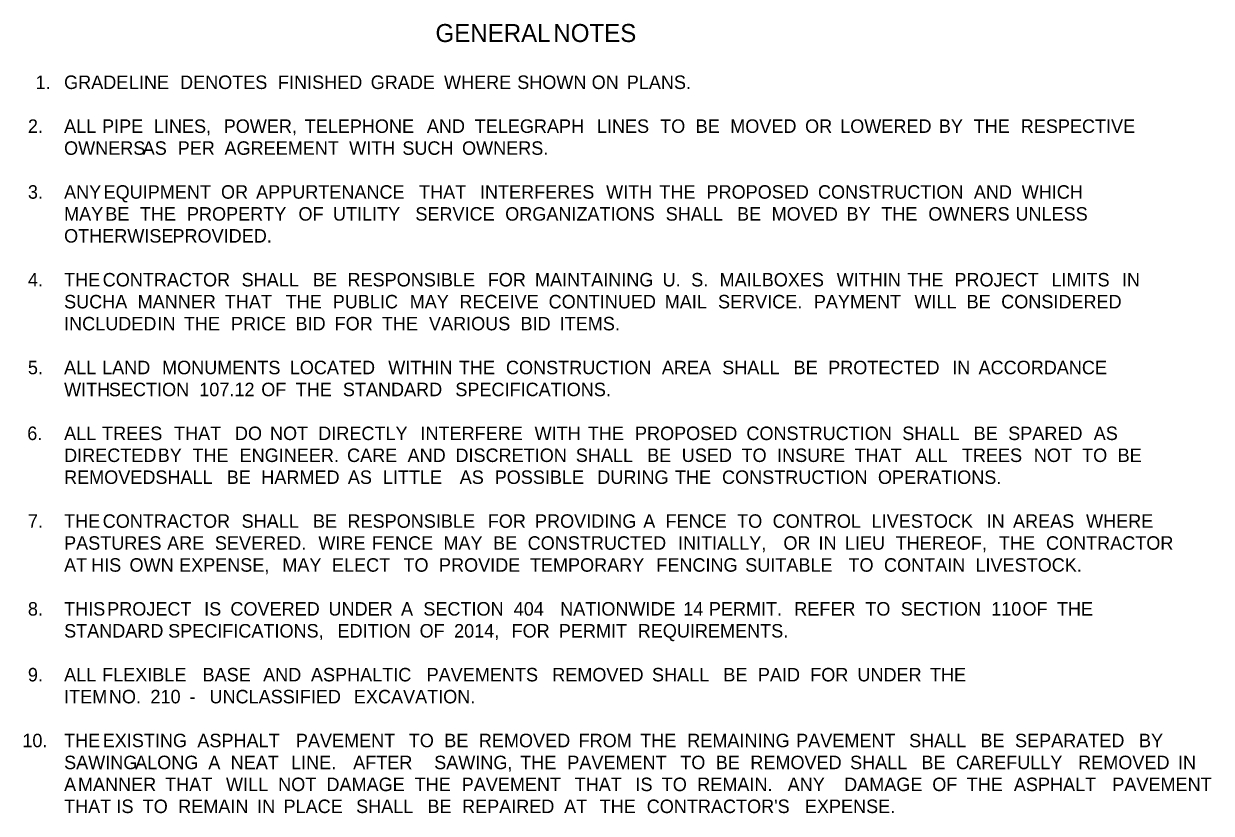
# Model space of a CAD drawing. Extents: x 1226673 to 1228148, y 151313 to 152324.
# Drawn here: x 1226673 to 1227200, y 151655 to 152006 of the extents above; entities that cross this region are included whole.
import ezdxf

# ---------------------------------------------------------------- set-up
doc = ezdxf.new("R2010")
doc.units = 0
doc.layers.add('R_Dimension', color=7, linetype='Continuous')

msp = doc.modelspace()

# ---------------------------------------------------------------- texts
at = {"layer": 'R_Dimension'}
for s, height, p in [('GENERAL', 8, (1226855.48, 151998.07)), (' NOTES', 8, (1226904.87, 151998.07)), ('1.', 6, (1226677.8, 151977.19)), ('GRADE', 6, (1226690.48, 151977.19)), (' LINE', 6, (1226717.03, 151977.19)), (' DENOTES', 6, (1226739.76, 151977.19)), (' FINISHED', 6, (1226783.27, 151977.19)), (' GRADE', 6, (1226824.47, 151977.19)), (' WHERE', 6, (1226857.02, 151977.19)), (' SHOWN', 6, (1226889.57, 151977.19)), (' ON', 6, (1226922.64, 151977.19)), (' PLANS.', 6, (1226938.23, 151977.19)), ('2.', 6, (1226674.4, 151957.69)), ('ALL', 6, (1226690.48, 151957.69)), (' PIPE', 6, (1226705.13, 151957.69)), (' LINES,', 6, (1226728.14, 151957.69)), (' POWER,', 6, (1226759.17, 151957.69)), (' TELEPHONE', 6, (1226795.13, 151957.69)), (' AND', 6, (1226849.41, 151957.69)), (' TELEGRAPH', 6, (1226870.67, 151957.69)), (' LINES', 6, (1226924.95, 151957.69)), (' TO', 6, (1226953.06, 151957.69)), (' BE', 6, (1226968.84, 151957.69)), (' MOVED', 6, (1226984.2, 151957.69)), (' OR', 6, (1227017.46, 151957.69)), (' LOWERED', 6, (1227033.05, 151957.69)), (' BY', 6, (1227076.89, 151957.69)), (' THE', 6, (1227092.34, 151957.69)), (' RESPECTIVE', 6, (1227113.27, 151957.69)), ('OWNERS', 6, (1226690.48, 151947.94)), (' AS', 6, (1226723.17, 151947.94)), (' PER', 6, (1226738.72, 151947.94)), (' AGREEMENT', 6, (1226759.51, 151947.94)), (' WITH', 6, (1226814.88, 151947.94)), (' SUCH', 6, (1226838.54, 151947.94)), (' OWNERS.', 6, (1226865.05, 151947.94)), ('3.', 6, (1226674.4, 151928.44)), ('ANY', 6, (1226690.48, 151928.44)), (' EQUIPMENT', 6, (1226705.79, 151928.44)), (' OR', 6, (1226757.95, 151928.44)), (' APPURTENANCE', 6, (1226773.54, 151928.44)), (' THAT', 6, (1226845.96, 151928.44)), (' INTERFERES', 6, (1226872.99, 151928.44)), (' WITH', 6, (1226929.06, 151928.44)), (' THE', 6, (1226952.73, 151928.44)), (' PROPOSED', 6, (1226973.66, 151928.44)), (' CONSTRUCTION', 6, (1227023.17, 151928.44)), (' AND', 6, (1227092.43, 151928.44)), (' WHICH', 6, (1227113.69, 151928.44)), ('MAY', 6, (1226690.48, 151918.69)), (' BE', 6, (1226706.54, 151918.69)), (' THE', 6, (1226721.9, 151918.69)), (' PROPERTY', 6, (1226742.83, 151918.69)), (' OF', 6, (1226792.39, 151918.69)), (' UTILITY', 6, (1226807.69, 151918.69)), (' SERVICE', 6, (1226844.31, 151918.69)), (' ORGANIZATIONS', 6, (1226884.23, 151918.69)), (' SHALL', 6, (1226955.52, 151918.69)), (' BE', 6, (1226987.22, 151918.69)), (' MOVED', 6, (1227002.58, 151918.69)), (' BY', 6, (1227035.84, 151918.69)), (' THE', 6, (1227051.29, 151918.69)), (' OWNERS', 6, (1227072.21, 151918.69)), (' UNLESS', 6, (1227110.91, 151918.69)), ('OTHERWISE', 6, (1226690.48, 151908.94)), (' PROVIDED.', 6, (1226736.4, 151908.94)), ('4.', 6, (1226674.4, 151889.44)), ('THE', 6, (1226690.48, 151889.44)), (' CONTRACTOR', 6, (1226705.41, 151889.44)), (' SHALL', 6, (1226767.11, 151889.44)), (' BE', 6, (1226798.81, 151889.44)), (' RESPONSIBLE', 6, (1226814.17, 151889.44)), (' FOR', 6, (1226876.48, 151889.44)), (' MAINTAINING', 6, (1226897.46, 151889.44)), (' U.', 6, (1226954.15, 151889.44)), (' S.', 6, (1226966.86, 151889.44)), (' MAILBOXES', 6, (1226979.47, 151889.44)), (' WITHIN', 6, (1227031.49, 151889.44)), (' THE', 6, (1227062.86, 151889.44)), (' PROJECT', 6, (1227083.79, 151889.44)), (' LIMITS', 6, (1227126.88, 151889.44)), (' IN', 6, (1227158.2, 151889.44)), ('SUCH', 6, (1226690.48, 151879.69)), (' A', 6, (1226710.99, 151879.69)), (' MANNER', 6, (1226720.91, 151879.69)), (' THAT', 6, (1226759.65, 151879.69)), (' THE', 6, (1226786.67, 151879.69)), (' PUBLIC', 6, (1226807.6, 151879.69)), (' MAY', 6, (1226841.8, 151879.69)), (' RECEIVE', 6, (1226863.87, 151879.69)), (' CONTINUED', 6, (1226903.51, 151879.69)), (' MAIL', 6, (1226955.1, 151879.69)), (' SERVICE.', 6, (1226978.77, 151879.69)), (' PAYMENT', 6, (1227021.33, 151879.69)), (' WILL', 6, (1227066.03, 151879.69)), (' BE', 6, (1227089.22, 151879.69)), (' CONSIDERED', 6, (1227104.58, 151879.69)), ('INCLUDED', 6, (1226690.48, 151869.94)), (' IN', 6, (1226729.74, 151869.94)), (' THE', 6, (1226741.46, 151869.94)), (' PRICE', 6, (1226762.39, 151869.94)), (' BID', 6, (1226791.06, 151869.94)), (' FOR', 6, (1226808.45, 151869.94)), (' THE', 6, (1226829.43, 151869.94)), (' VARIOUS', 6, (1226850.36, 151869.94)), (' BID', 6, (1226891.03, 151869.94)), (' ITEMS.', 6, (1226908.42, 151869.94)), ('5.', 6, (1226674.4, 151850.44)), ('ALL', 6, (1226690.48, 151850.44)), (' LAND', 6, (1226705.13, 151850.44)), (' MONUMENTS', 6, (1226731.77, 151850.44)), (' LOCATED', 6, (1226788.51, 151850.44)), (' WITHIN', 6, (1226832.26, 151850.44)), (' THE', 6, (1226863.63, 151850.44)), (' CONSTRUCTION', 6, (1226884.56, 151850.44)), (' AREA', 6, (1226953.82, 151850.44)), (' SHALL', 6, (1226980.66, 151850.44)), (' BE', 6, (1227012.36, 151850.44)), (' PROTECTED', 6, (1227027.71, 151850.44)), (' IN', 6, (1227082.8, 151850.44)), (' ACCORDANCE', 6, (1227094.51, 151850.44)), ('WITH', 6, (1226690.48, 151840.69)), (' SECTION', 6, (1226708.15, 151840.69)), (' 107.12', 6, (1226748.31, 151840.69)), (' OF', 6, (1226775.85, 151840.69)), (' THE', 6, (1226791.16, 151840.69)), (' STANDARD', 6, (1226812.09, 151840.69)), (' SPECIFICATIONS.', 6, (1226862.07, 151840.69)), ('6.', 6, (1226674.12, 151821.19)), ('ALL', 6, (1226690.48, 151821.19)), (' TREES', 6, (1226705.13, 151821.19)), (' THAT', 6, (1226737.11, 151821.19)), (' DO', 6, (1226764.14, 151821.19)), (' NOT', 6, (1226779.73, 151821.19)), (' DIRECTLY', 6, (1226801.17, 151821.19)), (' INTERFERE', 6, (1226846.58, 151821.19)), (' WITH', 6, (1226897.27, 151821.19)), (' THE', 6, (1226920.94, 151821.19)), (' PROPOSED', 6, (1226941.87, 151821.19)), (' CONSTRUCTION', 6, (1226991.38, 151821.19)), (' SHALL', 6, (1227060.64, 151821.19)), (' BE', 6, (1227092.34, 151821.19)), (' SPARED', 6, (1227107.69, 151821.19)), (' AS', 6, (1227145.68, 151821.19)), ('DIRECTED', 6, (1226690.48, 151811.44)), (' BY', 6, (1226729.84, 151811.44)), (' THE', 6, (1226745.29, 151811.44)), (' ENGINEER.', 6, (1226766.21, 151811.44)), (' CARE', 6, (1226813.98, 151811.44)), (' AND', 6, (1226840.86, 151811.44)), (' DISCRETION', 6, (1226862.12, 151811.44)), (' SHALL', 6, (1226915.6, 151811.44)), (' BE', 6, (1226947.3, 151811.44)), (' USED', 6, (1226962.66, 151811.44)), (' TO', 6, (1226989.21, 151811.44)), (' INSURE', 6, (1227004.99, 151811.44)), (' THAT', 6, (1227039.43, 151811.44)), (' ALL', 6, (1227066.45, 151811.44)), (' TREES', 6, (1227087.1, 151811.44)), (' NOT', 6, (1227119.08, 151811.44)), (' TO', 6, (1227140.53, 151811.44)), (' BE', 6, (1227156.31, 151811.44)), ('REMOVED', 6, (1226690.48, 151801.69)), (' SHALL', 6, (1226728.8, 151801.69)), (' BE', 6, (1226760.5, 151801.69)), (' HARMED', 6, (1226775.85, 151801.69)), (' AS', 6, (1226814.31, 151801.69)), (' LITTLE', 6, (1226829.85, 151801.69)), (' AS', 6, (1226864.01, 151801.69)), (' POSSIBLE', 6, (1226879.55, 151801.69)), (' DURING', 6, (1226925.14, 151801.69)), (' THE', 6, (1226959.63, 151801.69)), (' CONSTRUCTION', 6, (1226980.56, 151801.69)), (' OPERATIONS.', 6, (1227049.82, 151801.69)), ('7.', 6, (1226674.4, 151782.19)), ('THE', 6, (1226690.48, 151782.19)), (' CONTRACTOR', 6, (1226705.41, 151782.19)), (' SHALL', 6, (1226767.11, 151782.19)), (' BE', 6, (1226798.81, 151782.19)), (' RESPONSIBLE', 6, (1226814.17, 151782.19)), (' FOR', 6, (1226876.48, 151782.19)), (' PROVIDING', 6, (1226897.46, 151782.19)), (' A', 6, (1226945.55, 151782.19)), (' FENCE', 6, (1226955.47, 151782.19)), (' TO', 6, (1226987.27, 151782.19)), (' CONTROL', 6, (1227003.05, 151782.19)), (' LIVESTOCK', 6, (1227047.03, 151782.19)), (' IN', 6, (1227098.1, 151782.19)), (' AREAS', 6, (1227109.82, 151782.19)), (' WHERE', 6, (1227142.28, 151782.19)), ('PASTURES', 6, (1226690.48, 151772.44)), (' ARE', 6, (1226734.04, 151772.44)), (' SEVERED.', 6, (1226755.25, 151772.44)), (' WIRE', 6, (1226801.22, 151772.44)), (' FENCE', 6, (1226824.99, 151772.44)), (' MAY', 6, (1226856.78, 151772.44)), (' BE', 6, (1226878.84, 151772.44)), (' CONSTRUCTED', 6, (1226894.2, 151772.44)), (' INITIALLY,', 6, (1226961, 151772.44)), (' OR', 6, (1227007.82, 151772.44)), (' IN', 6, (1227023.41, 151772.44)), (' LIEU', 6, (1227035.13, 151772.44)), (' THEREOF,', 6, (1227057.66, 151772.44)), (' THE', 6, (1227103.54, 151772.44)), (' CONTRACTOR', 6, (1227124.47, 151772.44)), ('AT', 6, (1226690.48, 151762.69)), (' HIS', 6, (1226700.26, 151762.69)), (' OWN', 6, (1226717.32, 151762.69)), (' EXPENSE,', 6, (1226739.33, 151762.69)), (' MAY', 6, (1226785.21, 151762.69)), (' ELECT', 6, (1226807.27, 151762.69)), (' TO', 6, (1226839.02, 151762.69)), (' PROVIDE', 6, (1226854.8, 151762.69)), (' TEMPORARY', 6, (1226895.19, 151762.69)), (' FENCING', 6, (1226951.36, 151762.69)), (' SUITABLE', 6, (1226990.86, 151762.69)), (' TO', 6, (1227036.73, 151762.69)), (' CONTAIN', 6, (1227052.51, 151762.69)), (' LIVESTOCK.', 6, (1227093.14, 151762.69)), ('8.', 6, (1226674.4, 151743.19)), ('THIS', 6, (1226690.48, 151743.19)), (' PROJECT', 6, (1226707.4, 151743.19)), (' IS', 6, (1226750.48, 151743.19)), (' COVERED', 6, (1226762.15, 151743.19)), (' UNDER', 6, (1226805.71, 151743.19)), (' A', 6, (1226837.93, 151743.19)), (' SECTION', 6, (1226847.85, 151743.19)), (' 404', 6, (1226888.01, 151743.19)), (' NATIONWIDE', 6, (1226908.66, 151743.19)), (' 14', 6, (1226963.32, 151743.19)), (' PERMIT.', 6, (1226974.7, 151743.19)), (' REFER', 6, (1227012.64, 151743.19)), (' TO', 6, (1227044.2, 151743.19)), (' SECTION', 6, (1227059.98, 151743.19)), (' 110', 6, (1227100.14, 151743.19)), (' OF', 6, (1227114.03, 151743.19)), (' THE', 6, (1227129.33, 151743.19)), ('STANDARD', 6, (1226690.48, 151733.44)), (' SPECIFICATIONS,', 6, (1226734.47, 151733.44)), (' EDITION', 6, (1226809.73, 151733.44)), (' OF', 6, (1226846.2, 151733.44)), (' 2014,', 6, (1226861.51, 151733.44)), (' FOR', 6, (1226887.06, 151733.44)), (' PERMIT', 6, (1226908.04, 151733.44)), (' REQUIREMENTS.', 6, (1226943.1, 151733.44)), ('9.', 6, (1226674.4, 151713.94)), ('ALL', 6, (1226690.48, 151713.94)), (' FLEXIBLE', 6, (1226705.13, 151713.94)), (' BASE', 6, (1226749.77, 151713.94)), (' AND', 6, (1226776.66, 151713.94)), (' ASPHALTIC', 6, (1226797.92, 151713.94)), (' PAVEMENTS', 6, (1226849.32, 151713.94)), (' REMOVED', 6, (1226905.11, 151713.94)), (' SHALL', 6, (1226949.43, 151713.94)), (' BE', 6, (1226981.13, 151713.94)), (' PAID', 6, (1226996.48, 151713.94)), (' FOR', 6, (1227019.73, 151713.94)), (' UNDER', 6, (1227040.7, 151713.94)), (' THE', 6, (1227072.92, 151713.94)), ('ITEM', 6, (1226690.48, 151704.19)), (' NO.', 6, (1226708.15, 151704.19)), (' 210', 6, (1226726.62, 151704.19)), (' UNCLASSIFIED', 6, (1226752.84, 151704.19)), (' EXCAVATION.', 6, (1226817, 151704.19)), (' -', 6, (1226743.92, 151704.19)), ('10.', 6, (1226671.94, 151684.69)), ('THE', 6, (1226690.48, 151684.69)), (' EXISTING', 6, (1226705.41, 151684.69)), (' ASPHALT', 6, (1226747.46, 151684.69)), (' PAVEMENT', 6, (1226791.21, 151684.69)), (' TO', 6, (1226841.38, 151684.69)), (' BE', 6, (1226857.16, 151684.69)), (' REMOVED', 6, (1226872.51, 151684.69)), (' FROM', 6, (1226916.83, 151684.69)), (' THE', 6, (1226944.18, 151684.69)), (' REMAINING', 6, (1226965.11, 151684.69)), (' PAVEMENT', 6, (1227013.49, 151684.69)), (' SHALL', 6, (1227063.66, 151684.69)), (' BE', 6, (1227095.36, 151684.69)), (' SEPARATED', 6, (1227110.72, 151684.69)), (' BY', 6, (1227165.8, 151684.69)), ('SAWING', 6, (1226690.48, 151674.94)), (' ALONG', 6, (1226719.82, 151674.94)), (' A', 6, (1226752.32, 151674.94)), (' NEAT', 6, (1226762.25, 151674.94)), (' LINE.', 6, (1226789.08, 151674.94)), ('  AFTER', 6, (1226814.45, 151674.94)), (' SAWING,', 6, (1226852.67, 151674.94)), (' THE', 6, (1226890.89, 151674.94)), (' PAVEMENT', 6, (1226911.82, 151674.94)), (' TO', 6, (1226961.99, 151674.94)), (' BE', 6, (1226977.77, 151674.94)), (' REMOVED', 6, (1226993.13, 151674.94)), (' SHALL', 6, (1227037.44, 151674.94)), (' BE', 6, (1227069.14, 151674.94)), (' CAREFULLY', 6, (1227084.5, 151674.94)), (' REMOVED', 6, (1227138.78, 151674.94)), (' IN', 6, (1227183.1, 151674.94)), ('A', 6, (1226690.48, 151665.19)), (' MANNER', 6, (1226694.4, 151665.19)), (' THAT', 6, (1226733.14, 151665.19)), (' WILL', 6, (1226760.17, 151665.19)), (' NOT', 6, (1226783.36, 151665.19)), (' DAMAGE', 6, (1226804.81, 151665.19)), (' THE', 6, (1226843.98, 151665.19)), (' PAVEMENT', 6, (1226864.91, 151665.19)), (' THAT', 6, (1226915.08, 151665.19)), (' IS', 6, (1226942.1, 151665.19)), (' TO', 6, (1226953.77, 151665.19)), (' REMAIN.', 6, (1226969.55, 151665.19)), ('  ANY', 6, (1227007.49, 151665.19)), (' DAMAGE', 6, (1227034.8, 151665.19)), (' OF', 6, (1227073.96, 151665.19)), (' THE', 6, (1227089.27, 151665.19)), (' ASPHALT', 6, (1227110.2, 151665.19)), (' PAVEMENT', 6, (1227153.95, 151665.19)), ('THAT', 6, (1226690.48, 151655.44)), (' IS', 6, (1226711.51, 151655.44)), (' TO', 6, (1226723.17, 151655.44)), (' REMAIN', 6, (1226738.95, 151655.44)), (' IN', 6, (1226774.01, 151655.44)), (' PLACE', 6, (1226785.73, 151655.44)), (' SHALL', 6, (1226817.99, 151655.44)), (' BE', 6, (1226849.69, 151655.44)), (' REPAIRED', 6, (1226865.05, 151655.44)), (' AT', 6, (1226910.4, 151655.44)), (' THE', 6, (1226926.18, 151655.44)), (" CONTRACTOR'S", 6, (1226947.11, 151655.44)), (' EXPENSE.', 6, (1227017.36, 151655.44))]:
    msp.add_text(s, height=height, dxfattribs=at).set_placement(p)

doc.saveas('drawing.dxf')
